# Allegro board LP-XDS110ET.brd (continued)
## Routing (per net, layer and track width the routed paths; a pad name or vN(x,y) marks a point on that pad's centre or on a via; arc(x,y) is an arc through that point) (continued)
ET_PM2: length 40.8
  TOP w0.15: U5.76 13.25,33.17 v1(13.45,32.97) ; v1(45.95,43.97) R96.2 46.2,43.59 U35.17
  BOTTOM w0.15: v1(45.95,43.97) 45.3,43.32 40.56,43.32 39.2,41.96 39.2,41.02 36.66,38.48 36.66,38.47 36.09,37.89 31.96,37.89 28.81,34.75 24.12,34.75 23.32,33.94 14.42,33.94 v1(13.45,32.97)
ET_PN3: length 45.8
  TOP w0.15: v1(5.15,27.47) 4.75,27.47 4.67,27.39 U5.110 ; R114.2 39.43,39.67 v1(40.15,39.67) 40.25,39.77 U35.28
  BOTTOM w0.15: v1(5.15,27.47) 6.5,27.47 8.07,29.03 17.63,29.03 19.69,31.1 28.67,31.1 29.02,30.75 30.78,30.75 30.83,30.69 33.48,30.69 36.52,33.74 37,33.74 37.24,33.99 37.24,34.46 40.15,37.37 v1(40.15,39.67)
ET_SSICLK: length 50.1
  TOP w0.15: v1(43.7,41.67) U35.22 ; v1(5.2,23.92) 4.67,23.39 U5.120
  BOTTOM w0.15: v1(43.7,41.67) 43.7,41.35 41.42,39.07 41.42,38.22 37.54,34.34 37.54,33.86 37.12,33.44 36.65,33.44 33.05,29.85 29.02,29.85 28.31,30.56 25.1,30.56 24.72,30.18 21.21,30.18 20.43,29.4 19.92,29.4 18.4,27.88 9.16,27.88 v1(5.2,23.92)
ET_SSIDAT0: length 50.8
  TOP w0.15: v1(5.65,22.27) 4.72,22.27 4.64,22.19 U5.123 ; v1(44.2,41.47) U35.21
  BOTTOM w0.15: v1(5.65,22.27) 10.93,27.55 24.12,27.55 25.15,28.57 25.15,28.57 26.01,29.43 28.49,29.43 28.96,28.96 32.59,28.96 36.77,33.14 37.25,33.14 37.84,33.74 37.84,34.21 41.72,38.09 41.72,38.95 44.2,41.42 v1(44.2,41.47)
ET_SSIDAT1: length 52.8
  TOP w0.15: U5.124 4.66,21.79 v1(4.95,21.5) ; U35.20 v1(44.7,41.67)
  BOTTOM w0.15: v1(44.7,41.67) 44.7,40.69 43.15,39.14 43.15,37.04 40.07,33.97 40.07,33.79 39.83,33.55 39.65,33.55 38.74,32.63 38.35,32.63 34.36,28.65 34.21,28.65 34.2,28.64 28.86,28.64 28.36,29.13 26.13,29.13 25.27,28.27 25.27,28.27 24.19,27.19 11,27.19 6.65,22.85 6.65,22.62 5.52,21.5 v1(4.95,21.5)
ET_SSIFSS: length 54
  TOP w0.15: U35.19 45.2,41.5 v1(45.2,41.5) ; v1(6.95,22.12) 6.66,22.41 5.78,23.3 5.25,23.3 4.95,22.99 U5.121
  BOTTOM w0.15: v1(6.95,22.12) 6.95,22.72 11.12,26.89 22.4,26.89 22.73,26.57 27.31,26.57 28.53,27.79 33.95,27.79 33.95,27.79 34.19,27.79 34.2,27.8 34.56,27.8 34.81,28.05 34.81,28.11 35.42,28.72 35.42,29.25 38.51,32.33 38.87,32.33 39.78,33.25 39.95,33.25 40.38,33.67 40.38,33.84 44.88,38.35 44.93,38.35 45.17,38.59 45.17,38.64 45.2,38.67 v1(45.2,41.5)
ET_VDD: length 41.9
  TOP w0.15: R151.2 32.2,28.2 C172.1 32.2,26.97 31.6,26.37 29.4,26.37
  BOTTOM w1: 29.3,25.82 v1(29.3,25.12) ; 29.3,25.82 v1(29.3,26.32) ; 29.3,25.82 v1(28.8,26.32) 28.02,25.54 25.58,25.54 24.53,24.49 11.64,24.49 6.36,19.21 6.36,13.02 P9.1
ET_VREF: length 21.7
  TOP w0.3: U40.6 52.47,38.64 C146.1 51.82,38.64 U40.5 ; v1(41.24,26.22) R121.1 ; U35.9 48.65,37.77 48.95,37.47
  BOTTOM w0.3: v1(41.24,26.22) 42.23,27.21 42.23,27.45 44.7,29.92 44.7,30.76 45.87,31.94 47.08,31.94 49.95,34.8 v1(49.95,37.47)
IRSTN: length 23.9
  TOP w0.15: v1(20.24,34.99) 20.2,34.95 R20.2
  BOTTOM w0.15: v1(20.24,34.99) 19.55,34.99 18.87,34.3 10.88,34.3 8.58,32 4.1,32 2.88,33.23 2.88,33.75 3.48,34.35 3.48,36.31 3.32,36.47 P8.10
ITCK: length 11.6
  TOP w0.15: U5.100 2.93,31.39 v1(1.75,32.57)
  BOTTOM w0.15: P8.4 1.1,39.93 1.1,36.29 1.02,36.22 1.02,34.34 1.1,34.27 1.1,33.22 v1(1.75,32.57)
ITDI: length 10.3
  TOP w0.15: v1(3.3,33.57) 2.7,32.97 2.7,32.52 3.03,32.19 U5.98
  BOTTOM w0.15: v1(3.3,33.57) 3.7,33.57 4.26,34.13 4.42,34.13 4.92,34.63 4.92,37.48 4.56,37.85 4.56,38.37 P8.8
ITDO: length 11.2
  TOP w0.15: v1(3.75,33.07) 3.75,32.67 U5.97
  BOTTOM w0.15: v1(3.75,33.07) 4.51,33.83 4.54,33.83 5.22,34.51 5.22,34.54 5.36,34.68 5.36,37.79 5.41,37.85 5.41,38.23 5.39,38.24 5.39,38.6 5.43,38.63 5.43,40.04 P8.6
ITMS: length 8.4
  TOP w0.15: v1(1.81,33.56) 2.17,33.19 2.17,32.57 2.95,31.79 U5.99
  BOTTOM w0.15: P8.2 1.4,37.69 1.4,36.17 1.32,36.09 1.32,34.47 1.4,34.39 1.4,33.97 v1(1.81,33.56)
LP_VDD: length 10
  TOP w0.5: P7.1 v1(48.66,6.96)
  BOTTOM w0.15: 22.9,8.98 P10.5 ; P10.5 21.82,10.06 ; P10.5 23.98,10.06 ; P10.5 22.9,11.14 ; 9.26,3.97 P9.3 ; P9.3 8.19,5.04 ; P9.3 9.26,6.12 ; P9.3 10.34,5.04
  vias: v1(51.95,18.65) v1(51.95,18.12) v1(52.48,18.12)
LS_VDD: length 15.9
  TOP w0.15: C70.1 22.7,15.56
  TOP w0.2: C488.1 33.77,15.56 33.77,15.93 33.89,16.05 U49.2 ; C72.1 28.2,15.64 U10.2 ; U9.2 39.2,15.73 C74.1 ; 22.7,15.56 U8.2
  TOP w0.3: CR16.8 43.17,15.58 42.87,15.28 v1(42.87,15.1) ; 21.96,15.08 v1(21.96,14.43) ; 21.96,15.08 21.5,15.54 R61.2 ; 21.96,15.08 22.43,15.55 C70.1 ; U33.9 53.75,28.64 v1(53.7,28.69) ; v1(27.56,15.2) 27.82,15.46 27.84,15.46 27.92,15.55 C72.1 ; v1(54.45,24.32) 54.25,24.52 U33.3 ; v1(38.37,15.18) 38.74,15.55 C74.1 ; v1(33.19,15.21) 33.53,15.55 C488.1 ; CR7.8 46.64,15.58 46.34,15.28 v1(46.34,15.15)
  L3 w0.15: 9.26,6.5 P9.2 ; P9.2 9.26,8.66 ; P9.2 8.19,7.58 ; P9.2 10.34,7.58
SW_VDD: length 61.3
  TOP w0.15: U44.5 25.02,24.8 23.22,24.8 R134.2 ; U39.14 56.25,30.77 C140.1 v1(57.03,30.97)
  TOP w0.3: U33.1 53,25.27 C139.1 51.7,25.17 v1(50.75,25.17) ; U38.1 55.35,18.32 55.45,18.42 C114.1 v1(56.35,19.01)
  BOTTOM w0.3: 50.77,19.15 52.52,19.15 53.4,18.27 55.61,18.27 v1(56.35,19.01) 56.6,19.26 56.6,25.2 56.81,25.42 56.81,27.44 56.51,27.75 56.51,28.39 56.5,28.39 56.5,28.81 56.51,28.81 56.51,30.45 v1(57.03,30.97) ; 50.77,19.15 50.77,25.15 v1(50.75,25.17) ; 50.77,19.15 45.21,19.15 43.86,20.5 43.12,20.5 41.58,22.03 33.17,22.03 31.5,23.7 31.44,23.7 30.96,24.18 28.07,24.18 v1(27.55,24.69) v1(26.99,24.69) v1(26.37,24.69)
USB1V8: length 11.3
  TOP w0.15: v1(6.16,36.78) C83.1 5.94,37.21 C85.1 5.95,37.52 U15.15 ; v1(13.11,36.91) 12.98,36.91 12.83,37.06 C84.1 12.77,37.52 U15.26
  L3 w0.15: v1(6.16,36.78) 6.29,36.91 v1(13.11,36.91)
USB_VBUS: length 1.8
  TOP w0.15: v1(14.66,40.57) 14.67,40.57 ; 9.87,42.93 10.41,42.39 R82.2 ; CR6.6 v1(5.46,43.65)
  vias: v1(9.45,45.45) v1(9.45,44.6) v1(9.47,42.93) v1(10.44,45.46) v1(11.42,45.47) v1(12.44,45.47) v1(13.48,45.47) v1(13.48,44.6) v1(13.43,42.99) v1(14.63,41.12)
USBA1V8: length 1.9
  TOP w0.15: C86.1 12.98,38.8 C87.1 12.64,38.96 11.96,38.96 U15.29
USBCLK: length 5.7
  TOP w0.15: v1(6.16,35.61) 6.16,35.11 6.44,34.83 6.61,34.83 6.82,34.62 6.82,34.04 U5.92 ; v1(6.25,38.12) 6.35,38.02 U15.14
  L3 w0.15: v1(6.25,38.12) 6.25,37.72 5.77,37.24 5.77,37 5.74,36.96 5.74,36.61 6.16,36.18 v1(6.16,35.61)
USBD0: length 2.3
  TOP w0.15: U15.24 11.2,35.69 11.25,35.64 U5.81
USBD1: length 2.4
  TOP w0.15: U15.23 10.7,35.69 10.85,35.54 U5.82
USBD2: length 2.4
  TOP w0.15: U5.83 10.45,35.44 10.2,35.69 U15.22
USBD3: length 2.5
  TOP w0.15: U5.84 10.05,35.34 9.7,35.69 U15.21
USBD4: length 2.5
  TOP w0.15: U5.85 9.65,35.22 9.2,35.67 U15.20
USBD5: length 2.5
  TOP w0.15: U15.19 8.7,35.67 9.25,35.12 U5.86
USBD6: length 11
  TOP w0.15: U15.18 v1(8.2,35.37) ; U5.106 4.69,28.99 4.89,28.79 v1(6.47,28.79)
  L3 w0.15: v1(8.2,35.37) 8.2,30.51 v1(6.47,28.79)
USBD7: length 10
  TOP w0.15: v1(6.35,29.41) 5.14,29.41 5.12,29.39 5.01,29.39 4.99,29.37 4.63,29.37 4.61,29.39 U5.105 ; U15.17 7.7,35.5 v1(7.68,35.49)
  L3 w0.15: v1(7.68,35.49) 7.68,30.74 v1(6.35,29.41)
USBDIR: length 12.3
  TOP w0.15: U5.104 v1(4.81,29.79) ; v1(5.85,39.02) 6.33,39.02 6.33,39.02 U15.12
  L3 w0.15: v1(4.81,29.79) 5.21,29.79 5.47,30.05 5.47,31.27 5.14,31.61 5.14,37.63 5.39,37.89 5.39,38.6 5.81,39.02 v1(5.85,39.02)
USBDM: length 11.8
  TOP w0.15: U15.8 7.35,41.22 7.22,41.34 v1(6.14,41.34) 5.85,41.34 5.52,41.68 CR6.4 ; v1(11.59,42.97) 11.75,42.97 12.05,43.27 J1.C7 12.05,44.11 11.82,44.35 11.08,44.35 10.85,44.11 J1.C10
  BOTTOM w0.15: v1(11.59,42.97) 11.59,42.91 11.33,42.64 11.33,42.63 10.03,41.34 v1(6.14,41.34)
USBDP: length 13.3
  TOP w0.15: CR6.5 5.61,42.18 5.91,41.87 6.15,41.87 v1(6.15,41.87) 7.85,41.87 8.2,41.52 U15.7 ; v1(11.05,42.97) 10.99,43.03 10.74,43.03 10.45,43.32 J1.C11 10.45,44.32 10.79,44.66 12.11,44.66 12.45,44.32 J1.C6
  BOTTOM w0.15: v1(6.15,41.87) 9.96,41.87 v1(11.05,42.97)
USBNXT: length 12.6
  TOP w0.15: U15.11 v1(6.22,39.52) ; v1(5.05,30.4) 4.86,30.22 4.63,30.22 4.61,30.19 U5.103
  L3 w0.15: v1(5.05,30.4) 4.76,30.68 4.76,36.94 4.78,36.96 4.78,37.68 4.6,37.86 4.6,38.47 4.58,38.49 4.58,38.81 5.29,39.52 v1(6.22,39.52)
USBSTP: length 7.3
  TOP w0.15: v1(5.82,38.42) 5.88,38.42 6,38.54 6.43,38.54 6.45,38.52 U15.13 ; v1(6.59,35.28) 6.99,35.28 7.25,35.02 U5.91
  L3 w0.15: v1(6.59,35.28) 6.52,35.2 6.35,35.2 6.34,35.19 5.98,35.19 5.74,35.44 5.74,35.66 5.44,35.96 5.44,37.51 5.82,37.89 v1(5.82,38.42)
VCM: length 16.3
  TOP w0.2: 44.45,23.56 R109.2 ; 44.45,23.56 45.59,23.56 48,25.97 R111.2 ; 44.45,23.56 44.45,22.77 43.31,21.63 41.13,21.63 40.6,22.17 R100.1 40.25,22.22 R131.1 38.3,25.02 U41.1
XDS_BID_SCL: length 11.4
  TOP w0.15: 4.28,16.54 v1(4.28,17.65) ; U5.112 v1(4.77,26.59)
  BOTTOM w0.15: v1(4.77,26.59) 4,25.82 4,17.93 v1(4.28,17.65)
XDS_BID_SCL_LS: length 35.8
  TOP w0.3: U50.8 v1(2.33,15.15)
  L3 w0.15: P10.6 21.63,11.33 21.63,8.07 17.25,3.69 8.43,3.69 6.04,6.08 6.04,8.45 1.91,12.58 1.91,14.72 v1(2.33,15.15)
XDS_BID_SDA: length 16.7
  TOP w0.15: U5.111 2.91,26.99 v1(2.89,27.01)
  TOP w0.3: v1(5.09,13.54) 4.79,13.24 4.52,13.24 4.28,13
  BOTTOM w0.15: v1(5.09,13.54) 4.5,13.54 3.21,14.84 3.21,25.67 2.89,25.99 v1(2.89,27.01)
XDS_BID_SDA_LS: length 32
  TOP w0.3: U50.1 v1(2.33,14.14)
  L3 w0.15: P10.4 19.21,11.45 19.21,6.8 16.41,3.99 8.55,3.99 6.34,6.21 6.34,8.58 2.33,12.58 v1(2.33,14.14)
XDS_DIR_GPIO1: length 75.4
  TOP w0.15: U49.4 34.69,17.09 34.54,17.24 v1(34.32,17.24) ; U5.116 4.8,24.99 4.92,24.87 v1(5.32,24.87)
  L3 w0.15: v1(36.86,10.46) 36.86,9.83 30.12,3.09 8.18,3.09 5.44,5.83 5.44,7.52 1.31,11.65 1.31,17.13 1.84,17.66 1.84,20.71 4.09,22.96 4.09,24.14 4.82,24.87 v1(5.32,24.87)
  BOTTOM w0.15: v1(36.86,10.46) 36.09,11.23 35.06,11.23 34.25,12.04 34.25,13.34 34.7,13.79 34.7,14.25 34.16,14.78 33.02,14.78 33.01,14.79 32.05,14.79 31.59,15.25 31.59,16.81 32.62,17.83 33.73,17.83 v1(34.32,17.24)
XDS_DIR_GPIO2: length 64.4
  TOP w0.15: U5.117 4.67,24.59 4.9,24.36 v1(4.91,24.36) ; U49.5 35.94,16.74 36.17,16.51 36.17,15.08 34.25,13.16 v1(34.25,9.07)
  L3 w0.15: v1(4.91,24.36) 4.57,24.02 4.57,22.92 2.18,20.53 2.18,17.57 1.61,17 1.61,11.77 5.74,7.65 5.74,5.96 8.3,3.39 29.73,3.39 34.25,7.91 v1(34.25,9.07)
XDS_GPIO1: length 21.3
  TOP w0.15: U49.7 35.9,17.54 36.05,17.69 36.05,18.95 35.07,19.92 31.7,19.92 31.61,20.02 25.83,20.02 23.29,22.56 23.29,22.77 21.87,24.19 U5.43
XDS_GPIO1_LS: length 21.2
  TOP w0.15: R11.2 31.86,16.48 v1(32.09,16.7) ; CR16.1 43.54,12.45 42.64,11.55 39.19,11.55 P10.18
  TOP w0.2: R11.2 31.46,17.22 R12.1
  BOTTOM w0.15: v1(32.09,16.7) 32.37,16.99 32.99,16.99 35,14.98 35,13.66 34.55,13.22 34.55,12.17 35.16,11.55 37.09,11.55 P10.18
XDS_GPIO2: length 20.5
  TOP w0.15: U5.44 21.9,24.59 23.59,22.89 23.59,22.68 25.96,20.32 31.73,20.32 31.82,20.23 v1(35.36,20.23) ; U49.8 v1(35.36,18.43)
  BOTTOM w0.15: v1(35.36,20.23) 35.36,19.83 35.36,19.83 v1(35.36,18.43)
XDS_GPIO2_LS: length 22.9
  TOP w0.15: CR16.2 44.04,12.53 42.77,11.25 36.95,11.25 P10.16
  TOP w0.2: R13.1 31.43,18.36 31.43,18.37 R10.2 v1(31.43,19.59)
  BOTTOM w0.15: P10.16 35.6,16.64 33.7,18.53 33.15,18.53 32.1,19.59 v1(31.43,19.59)
XDS_GPIO3: length 42.6
  TOP w0.15: R360.2 6.44,15.94 6.83,15.54 6.83,15.42 v1(7.33,14.92)
  TOP w0.2: v1(23.19,17.38) 23.22,17.41 23.49,17.41 23.62,17.54 U8.7 ; v1(20.24,23.64) 20.19,23.64 20.04,23.79 U5.42
  BOTTOM w0.15: v1(20.24,23.64) 11.82,23.64 7.08,18.91 7.08,15.16 v1(7.33,14.92) 7.33,14.16 7.66,13.82 10.39,13.82 15.36,18.79 22.28,18.79 23.19,17.88 v1(23.19,17.38)
XDS_GPIO3_LS: length 52.7
  TOP w0.15: CR16.3 v1(44.54,14.06) ; P10.12 29.03,11.11 27.54,11.11 26.74,10.3 v1(26.74,7.28) 18.42,7.28 16.31,9.4 16.31,14.32 19.8,17.81 R15.1
  BOTTOM w0.15: v1(44.54,14.06) 44.54,10.98 41.12,7.56 33.27,7.56 33.19,7.64 29.31,7.64 28.81,7.15 27.27,7.15 27.14,7.28 v1(26.74,7.28)
XDS_NCS: length 2.2
  TOP w0.15: U5.6 7.25,17.7 6.44,16.88 R360.1
XDS_PICO: length 16.4
  TOP w0.15: U5.11 9.25,19.5 9.27,19.52 9.27,20.43 v1(9.84,20.99) ; R361.1 v1(22.57,22.34)
  BOTTOM w0.15: v1(9.84,20.99) 9.83,20.99 10.13,21.29 18.28,21.29 18.66,21.67 21.24,21.67 21.91,22.34 v1(22.57,22.34)
XDS_POCI: length 9
  TOP w0.15: U5.27 15.65,19.67 v1(15.66,19.68) ; R362.1 v1(22.5,21.43)
  BOTTOM w0.15: v1(22.5,21.43) 20.75,19.68 v1(15.66,19.68)
XDS_RESET: length 21.1
  TOP w0.15: U5.40 22.52,22.99 22.99,22.51 22.99,22.43 25.75,19.67 29.35,19.67 30.23,18.79 30.38,18.79 v1(30.51,18.65) 30.63,18.54 R363.1 ; U10.1 27.8,16.06 27.34,15.6 R58.1
  TOP w0.3: v1(26.82,16.09) 26.82,15.71 R58.1
  BOTTOM w0.15: v1(26.82,16.09) 26.85,16.12 26.85,16.69 28.34,18.18 30.04,18.18 v1(30.51,18.65)
XDS_RESET_LS: length 79.3
  TOP w0.15: U10.15 26.55,17.14 26.31,17.38 v1(26.31,18.13)
  TOP w0.2: CR7.2 47.52,14.2 47.16,13.84 46.9,13.84 v1(46.59,13.53) ; P7.10 53.74,11.56 52.8,10.62 v1(50.93,10.62)
  TOP w0.3: R57.1 v1(29.81,44.07)
  L3 w0.15: v1(29.81,44.07) 29.87,44.13 33.51,44.13 33.81,43.83 33.81,20.6 33.22,20 27.64,20 26.31,18.68 v1(26.31,18.13) ; v1(46.59,13.53) 44.5,11.45 31.91,11.45 P10.11
  BOTTOM w0.15: P10.11 29.47,11.11 29.42,11.11 29.2,11.34 27.35,11.34 26.92,11.77 26.92,14.47 25.99,15.4 25.99,17.81 v1(26.31,18.13)
  BOTTOM w0.2: v1(50.93,10.62) 49.5,10.62 v1(46.59,13.53)
XDS_RX: length 7.5
  TOP w0.15: U8.8 24.18,18.27 24.7,18.79 24.7,19.25 23.76,20.19 U5.33
XDS_RX_LS: length 58.5
  TOP w0.15: R61.1 20.26,15.54 R359.2 ; U8.13 v1(21.63,18.37) 19.87,18.37 16.01,14.51 16.01,9.27 18.43,6.85 27.17,6.85 v1(27.94,7.62)
  TOP w0.2: CR16.6 v1(44.04,17.77) ; P10.9 27.94,10.02 v1(27.94,7.62)
  TOP w0.3: R61.1 v1(20.26,16.44)
  BOTTOM w0.15: v1(20.26,16.44) 21.63,17.81 v1(21.63,18.37)
  BOTTOM w0.2: v1(44.04,17.77) 44.04,10.94 41.26,8.16 28.47,8.16 v1(27.94,7.62)
XDS_SCLK: length 2.4
  TOP w0.15: R365.1 5.67,16.89 6.85,18.07 U5.5
XDS_SWO: length 12.2
  TOP w0.15: U8.9 23.67,18.21 24.22,18.76 24.22,19.3 23.71,19.81 16.21,19.81 15.9,20.11 15.39,20.11 14.85,19.57 U5.25
XDS_SWO_LS: length 48.3
  TOP w0.15: v1(42.99,16.3) 43.51,16.3 CR16.7 ; v1(21.68,19.34) 21.91,19.11 R62.2
  TOP w0.2: U8.12 22.3,19.1 R62.2
  BOTTOM w0.15: v1(42.99,16.3) 43.5,15.78 43.5,10.86 41.2,8.55 32.23,8.55 31.76,9.02 31.76,10.96 31.41,11.31 29.94,11.31 29.46,11.79 28.8,11.79 P10.10 27.98,15.01 27.99,15.02 27.99,15.77 29.79,17.57 30.21,17.57 30.95,18.31 30.95,19.14 30.86,19.23 30.86,21.69 30.34,22.2 24.55,22.2 v1(21.68,19.34)
XDS_TCK: length 45.6
  TOP w0.15: v1(7.85,14.37) 7.24,14.37 5.67,15.94 5.67,15.95
  TOP w0.2: U5.35 v1(20.03,20.99) ; U9.6 v1(41.34,17.14)
  BOTTOM w0.15: v1(41.34,17.14) 40.94,17.14 40.57,16.78 35.99,16.78 34.62,18.15 34.62,18.97 33.58,20.01 33.02,20.01 30.44,22.59 24.45,22.59 23.74,21.88 22.2,21.88 21.31,20.99 v1(20.03,20.99) 14.15,20.99 10.53,17.37 10.53,15.38 9.52,14.37 v1(7.85,14.37)
XDS_TCK_LS: length 31.7
  TOP w0.15: R16.1 36.57,15.06 34.55,13.04 34.55,11.11 P10.15
  TOP w0.2: P7.4 v1(49.93,11.57) ; CR7.6 v1(47.52,17.07)
  L3 w0.15: v1(49.93,11.57) 49.47,11.11 36.65,11.11 P10.15
  BOTTOM w0.2: v1(49.93,11.57) 49.93,13.6 47.52,16.01 v1(47.52,17.07)
XDS_TDI: length 28.1
  TOP w0.15: v1(42.07,17.54) 41.64,17.54 41.62,17.57 41.16,17.57 41.14,17.54 U9.7 ; U5.38 19.78,22.19 19.91,22.06 20.32,22.06 20.34,22.08 20.57,22.08 v1(20.59,22.1) 20.83,22.34 R361.2
  BOTTOM w0.15: v1(42.07,17.54) 41.64,17.54 41.62,17.57 39.44,17.57 39.38,17.63 35.56,17.63 34.92,18.27 34.92,19.1 33.7,20.31 33.14,20.31 30.57,22.89 23.41,22.89 23.41,22.88 21.38,22.88 v1(20.59,22.1)
XDS_TDI_LS: length 31.6
  TOP w0.15: CR7.3 48.02,14.23 43.85,10.06 P10.19
  TOP w0.2: R9.1 v1(36.57,18.09) ; CR7.3 51.31,14.83 52.47,13.67 P7.8
  BOTTOM w0.15: v1(36.57,18.09) 37.46,18.98 38.39,18.98 38.95,18.42 42.33,18.42 42.8,17.95 42.8,17.24 42.37,16.82 42.31,16.82 42.1,16.6 42.1,16.35 42.08,16.34 42.08,16.26 41.87,16.05 41.87,11.25 P10.19
XDS_TDO: length 30.3
  TOP w0.15: U5.37 19.72,21.79 19.75,21.76 20.29,21.76 20.62,21.43 R362.2
  TOP w0.2: U5.37 18.32,21.79 18.29,21.75 v1(18.14,21.75) ; v1(41.13,18.87) 40.56,18.29 40.09,18.29 U9.9
  BOTTOM w0.15: v1(41.13,18.87) 41.13,19.65 40.13,20.66 33.22,20.66 30.69,23.19 23.29,23.19 23.28,23.18 21.25,23.18 21.05,22.99 19.38,22.99 v1(18.14,21.75)
XDS_TDO_LS: length 39.3
  TOP w0.2: U9.12 38.81,18.21 R63.2 38.77,19.11 v1(38.22,18.56) ; P7.6 51.2,11.76 v1(50.93,11.49) ; CR7.5 v1(48.63,16.33)
  L3 w0.15: P10.17 38.14,9.03 38.41,8.76 48.2,8.76 v1(50.93,11.49)
  BOTTOM w0.15: v1(38.22,18.56) 38.65,18.12 42.2,18.12 42.5,17.83 42.5,17.37 42.25,17.12 42.19,17.12 41.8,16.73 41.8,16.48 41.78,16.46 41.78,16.39 41.57,16.18 41.57,15.11 40.25,13.79 40.25,13.78 40,13.53 39.99,13.53 39.29,12.83 39.29,11.21 P10.17
  BOTTOM w0.2: v1(48.63,16.33) 49.18,16.33 50.93,14.59 v1(50.93,11.49)
XDS_TMS: length 12.6
  TOP w0.15: U10.8 29.68,18.83 29.18,19.33 25.47,19.33 23.88,20.92 20.7,20.92 20.21,21.42 19.9,21.42 19.87,21.39 U5.36
XDS_TMS_DIR: length 37.8
  TOP w0.15: U5.24 14.45,17.97 15.52,16.9 15.52,16.12 15.71,15.93 15.71,9.15 18.32,6.53 30.13,6.53 31.68,8.09 31.68,13.93 30.99,14.62 30.16,14.62 30.01,14.77 30.01,16.1 29.68,16.44 U10.5
XDS_TMS_LS: length 44.4
  TOP w0.15: P7.2 48.66,12.17 48.04,11.55 v1(47.14,11.55) 43.98,8.39 33.7,8.39 33.06,9.03 P10.13 ; R65.2 25.72,17.5 25.19,16.98 25.19,16.66 24.63,16.1 24.63,14.35 24.38,14.1 v1(24.38,13.7)
  TOP w0.2: CR7.7 v1(46.53,16.33)
  TOP w0.3: R8.1 25.72,18.06 25.72,18.06 R65.2
  L3 w0.15: v1(24.38,13.7) 24.38,9.64 25.14,8.88 31.88,8.88 P10.13
  BOTTOM w0.2: v1(47.14,11.55) 46.09,12.6 46.09,14.1 46.79,14.79 46.79,15.33 46.53,15.59 v1(46.53,16.33)
XDS_TX: length 9.5
  TOP w0.15: U5.34 19.87,20.59 19.9,20.56 23.81,20.56 25.13,19.24 25.13,18.62 24.89,18.38 24.89,17.25 24.78,17.14 U8.6
XDS_TX_LS: length 43.9
  TOP w0.15: CR16.5 v1(45.03,16.33)
  TOP w0.2: R14.1 20.2,17.11 19.22,16.12 19.22,12.17 19.96,11.43 24.07,11.43 P10.7
  BOTTOM w0.15: v1(45.03,16.33) 45.03,15.93 45.05,15.91 45.05,9.31 42.53,6.79 30.73,6.79 30.36,6.42 26.38,6.42 25.44,7.36 P10.7
XDS_VDD: length 60.4
  TOP w0.15: 12.76,40.62 12.76,40.26 12.53,40.02 U15.31 U15.30 ; 12.76,40.62 C80.1 ; 12.76,40.62 13.06,40.32 13.42,40.32 13.51,40.22 v1(13.57,40.22) ; U15.6 8.7,41.87 8.67,41.9 R83.1 ; R17.2 18.87,34.76 18.52,35.11 v1(18.13,35.11) ; 6.45,36.16 6.72,35.89 v1(6.72,35.79) ; 6.45,36.16 C6.1 ; 6.45,36.16 6.5,36.16 7,36.67 U15.16 ; R83.1 8.67,42.71 v1(8.52,42.86) ; R83.1 C79.1 ; C39.1 15.15,35.57 15.63,35.09 15.77,35.09 16.05,34.81 U5.69 ; C39.1 15.25,35.58 15.81,36.14 R31.2 ; C39.1 14.72,35.14 v1(14.38,35.14) ; v1(1.65,26.37) C4.1 ; U5.122 5.32,22.59 v1(5.6,22.87) ; v1(12.18,36.29) 12.76,36.29 C78.1 12.83,36.25 12.42,36.65 12.42,36.77 12.17,37.02 U15.25 ; v1(20.21,25.87) 20.13,25.79 U5.47 ; C7.1 C42.1 8.15,16.87 8.57,16.45 R18.2 v1(8.85,15.77) ; R27.1 22.6,31.62 v1(22.85,31.87) ; R39.1 v1(22.84,32.42) ; U5.79 12.05,34.81 12.69,35.45 v1(13.2,35.45)
  TOP w0.2: U5.7 U5.8 8.05,17.79 8.05,17.44 C42.1 ; v1(16.08,16.68) 16.08,16.76 16.05,16.79 C2.1 ; C3.1 2.79,31.07 2.87,30.99 U5.101 ; U10.4 29,15.57 C73.1 28.8,15.55 28.6,15.75 U10.3 ; C71.1 23.5,15.56 ; 23.5,15.56 U8.4 ; 23.5,15.56 23.1,15.96 U8.3 ; C2.1 16.04,17.25 15.63,17.67 15.63,17.74 15.3,18.07 15.3,18.1 15.25,18.15 U5.26 ; C2.1 16.05,17.87 16.05,17.87 U5.28 ; U5.16 11.25,19.52 10.8,19.97 v1(10.55,19.97) ; U5.90 7.65,33.38 7.14,32.87 v1(7.05,32.87) ; U49.3 34.29,16.05 34.5,15.84 C487.1 ; v1(21.65,28.12) C40.1 C38.1 19.98,27.47 19.9,27.39 U5.51 U5.52 ; U5.39 19.93,22.59 20.01,22.51 20.1,22.51 v1(20.12,22.49) ; U9.4 40,15.78 C75.1 39.6,15.71 U9.3 ; U5.113 2.91,26.19 2.73,26.37 C4.1
  TOP w0.3: v1(25.42,15.74) 25.56,15.74 25.71,15.6 R58.2 ; C487.1 34.64,15.55 34.88,15.78 35,15.78 v1(35.05,15.83) ; v1(24.08,15.89) 23.74,15.55 C71.1 ; C3.1 v1(1.72,31.07) ; v1(4.24,11.74) C11.1 3.63,11.81 U50.3 ; C73.1 29.25,15.55 v1(29.54,15.83) ; C75.1 40.17,15.55 v1(40.45,15.83) ; U50.6 v1(3.63,15.53)
  L3 w1: v1(3.63,15.53) 3.63,14.7 4.05,14.29 4.05,14.27 4.24,14.08 v1(4.24,11.74)
  BOTTOM w0.15: v1(2.58,37.81) 2.58,37.73 2.56,37.71 2.56,37.53 P8.1
  vias: v1(22.72,36.47) v1(23.52,35.98) v1(23.52,35.42) v1(24.14,35.98) v1(24.14,35.42)
N2777344: length 2.7
  TOP w0.15: R57.2 29.04,45.46 29.06,45.48 SW3.3
N2941019: length 2.1
  TOP w0.15: R90.2 4.77,35.7 5.65,34.82 U5.95
N2941087: length 1.4
  TOP w0.15: R91.2 4.77,34.19 4.95,34.01 U5.96
N2941323: length 5.2
  TOP w0.15: R25.2 4.25,19.06 4.8,19.61 6.3,19.61 6.45,19.46 U5.4
N2941987: length 6.7
  TOP w0.15: U15.28 12.02,38.4 14.08,38.4 14.3,38.61 R87.2 14.84,38.62 15.47,39.25 15.47,39.25 15.72,39.5 15.72,39.5 15.79,39.57 16.09,39.57 16.19,39.48 C89.1 17.05,39.48 Y4.1
N2942075: length 8.6
  TOP w0.15: Y4.3 19.75,36.4 18.55,37.6 16.4,37.6 16.38,37.62 C88.2 15.44,37.62 15.38,37.69 R87.1 14.39,37.69 14.06,38.02 U15.27
N2942253: length 1.1
  TOP w0.15: U15.5 9.2,41.87 9.23,41.9 R83.2
N2942419: length 2.7
  TOP w0.15: R39.2 21.16,32.42 20.92,32.19 U5.63
N2942527: length 1.5
  TOP w0.15: U15.32 11.9,40.97 12.3,41.37 R84.2
N2942551: length 2.7
  TOP w0.15: R27.2 21.12,31.62 20.95,31.79 U5.62
N2942639: length 2.6
  TOP w0.15: R29.1 21.34,30.67 20.62,31.39 U5.61
N2942779: length 2.8
  TOP w0.15: R30.1 21.34,29.77 20.12,30.99 U5.60
N2943199: length 2.4
  TOP w0.15: R31.1 C46.1 16.64,35.11 16.45,34.92 U5.68
N2943999: length 6.2
  TOP w0.15: 19.2,33.61 R20.1 ; 19.2,33.61 v1(19.2,33.37) ; 19.2,33.61 18.87,33.94 R17.1 ; U5.70 15.65,33.07 v1(15.65,33.07)
  BOTTOM w0.15: v1(15.65,33.07) 16.15,33.57 19,33.57 v1(19.2,33.37)
N2944041: length 6
  TOP w0.15: U5.9 8.45,17.78 8.85,17.38 R18.1 9.6,17.37 C8.1 9.65,16.52 C50.1 10.3,15.87 U6.3
N2944509: length 13.1
  TOP w0.15: U5.88 8.45,32.85 7.67,32.07 5.6,32.07 3.51,34.17 3.51,36.15 3,36.66 1.99,36.66 1.43,37.22 C9.1 1.4,37.24 Y3.1
N2944561: length 14.3
  TOP w0.15: Y3.3 4.7,40.18 4.72,40.16 C1.1 5.17,40.15 4.65,39.63 4.65,39.63 4.53,39.51 4.53,37.45 4.29,37.2 4.18,37.2 3.94,36.95 3.94,36.85 3.81,36.72 3.81,34.37 5.79,32.38 7.38,32.38 8.05,33.05 U5.89
N2944733: length 3.2
  TOP w0.15: R28.2 20.67,29.57 20.67,30 20.09,30.58 20.09,30.59 U5.59
N2986125: length 14.6
  TOP w0.15: U34.6 U34.7 U34.8 44.2,46.32 44.95,47.07
  TOP w0.4: C118.1 44.95,47.07 45,47.02 v1(45,46.47)
  BOTTOM w0.4: v1(34.35,49.22) 38,49.22 40.75,46.47 v1(45,46.47)
N2986433: length 4
  TOP w0.15: R107.2 53.95,22.24 53.78,22.07 R99.2
N2986453: length 4.4
  TOP w0.15: Y5.3 41.1,48.72 41.75,48.07 43.21,48.07 44.2,49.06 U34.1
N2986493: length 0.5
  TOP w0.15: U34.2 U34.3
N2986501: length 1
  TOP w0.15: R94.2 U34.5
N2986505: length 1.6
  TOP w0.15: U35.24 R94.1
N2986529: length 15.3
  TOP w0.15: R107.1 53.95,20.9 53.68,21.17 R108.2
  TOP w0.3: 55.15,20.12 55.15,20.32 57.05,22.22 57.05,27.11 55.5,28.66 55,28.66 54.75,28.41 U33.7
N2986711: length 5.8
  TOP w0.15: R101.1 43.45,26.57 C129.1 43.4,26.72 R102.2 42.35,26.72 41.85,27.22 41.85,28.22 R95.2
N2986719: length 3.5
  TOP w0.15: R104.2 42.75,32.87 R103.1 40.5,30.62 R95.1
N2986959: length 4.5
  TOP w0.15: C123.1 42.23,29.57 42.58,29.22 U37.4 43.5,28.77 C130.1 R102.1
N2986967: length 3
  TOP w0.15: R103.2 42.7,31.07 U37.1 42.53,30.72 42.31,30.49 C123.2
N2987171: length 2.5
  TOP w0.15: U35.29 40.32,39.27 40.3,39.24 39.97,39.24 39.96,39.26 39.54,39.26 39.53,39.24 39.32,39.24 39.25,39.17 R97.1
N2987283: length 3.4
  TOP w0.15: U36.3 48.13,22.23 48.14,22.24 48.92,22.24 C132.1 49.13,22.08 ; 49.13,22.08 49.14,22.07 R99.1 ; 49.13,22.08 49.12,22.09 49.12,22.5 C124.2
N2987343: length 1.6
  TOP w0.15: U35.8 46.88,35.64 R98.2
N2987399: length 1.3
  TOP w0.15: U36.1 47.49,18.93 R137.2
N2987403: length 5.4
  TOP w0.15: U36.8 43.23,19.69 43.24,19.69 45.3,19.69 46.47,18.52 R137.1
N2987531: length 3.6
  TOP w0.2: R101.2 43.45,22.72 42.96,22.24 42.09,22.24 U36.6
N2987583: length 2.9
  TOP w0.15: R104.1 42.95,34.17 C131.1 43.7,34.92 U35.3
N2987595: length 1.5
  TOP w0.15: U35.23 43.2,43.55 R105.2
N2987655: length 3.7
  TOP w0.15: 49.15,21.13 49.1,21.19 C132.2 ; 49.15,21.13 49.4,21.13 49.44,21.17 R108.1 ; 49.15,21.13 49.1,21.13 ; 49.1,21.13 49.16,21.07 49.16,20.33 C134.1 ; 49.1,21.13 48.93,20.97 48.63,20.97 48.63,20.96 U36.2
N2987667: length 4.8
  TOP w0.15: R111.1 C133.1 47.25,28.27 v1(47.4,28.42) ; U37.7 45.35,29.72 v1(45.67,30.05)
  BOTTOM w0.15: v1(45.67,30.05) 45.77,30.05 v1(47.4,28.42)
N2987683: length 2.9
  TOP w0.15: U35.4 44.2,34.92 C131.2 44.95,34.17 R113.1
N2987711: length 2.3
  TOP w0.15: U36.5 42.41,23.5 42.41,23.5 40.96,23.5 R100.2
N2987751: length 4.5
  TOP w0.15: R110.1 C130.2 44.4,28.8 U37.6 45.29,29.22 45.64,29.57 C135.1
N2987759: length 3.1
  TOP w0.15: C135.2 45.63,30.49 45.4,30.72 U37.9 45.15,31.05 R112.2
N2987811: length 2.5
  TOP w0.15: U35.2 43.2,35.63 42.14,34.57 C136.1
N2987883: length 5.7
  TOP w0.15: R109.1 44.45,26.57 C129.2 44.5,26.72 R110.2 46.05,27.42 46.05,28.22 R120.2
N2987963: length 1.8
  TOP w0.15: C137.1 48.81,38.88 48.36,38.88 48.25,38.77 U35.11
N2988091: length 3.5
  TOP w0.15: R120.1 47.4,30.57 R112.1 45.1,32.87 R113.2
N2988111: length 1.8
  TOP w0.15: C138.1 41.05,41.27 U35.25
N2988211: length 4.8
  TOP w0.15: R116.2 48.55,36.32 47.35,36.32 46.4,37.27 45.96,37.27 45.7,37.01 U35.7
N2988383: length 2
  TOP w0.15: U35.16 48.13,41.27 R117.2
N2988415: length 1.9
  TOP w0.15: U35.15 48.38,40.77 R118.2
N2988503: length 1.8
  TOP w0.15: U35.12 48.43,39.27 R119.2
N2988673: length 17.1
  TOP w0.15: 54.48,30.64 v1(54.5,30.62) ; v1(54.9,19.07) 54.45,18.62 U38.2
  TOP w0.2: U39.2 54.9,31.07 54.5,30.67 v1(54.5,30.62) ; U39.9 54.1,30.07 54.48,30.45 54.48,30.72 54.45,30.72 54.1,31.07 U39.4
  BOTTOM w0.3: v1(54.9,19.07) 53.15,20.82 53.15,29.27 v1(54.5,30.62)
N2989115: length 3.5
  TOP w0.15: U39.1 55.3,31.94 54.42,32.82 ; 54.42,32.82 C143.1 ; 54.42,32.82 55.8,32.82 R123.2
N2989191: length 1.4
  TOP w0.3: U40.3 52.47,45.92 R136.2
N2989203: length 4.2
  TOP w0.15: R121.2 R126.1 38.5,28.37 ; U41.3 38.5,28.37 ; 38.5,28.37 C147.1
N2989279: length 1.1
  TOP w0.3: U40.4 C145.1
N2989287: length 1.8
  TOP w0.5: C146.2 54.95,39.32 R122.2
N2989331: length 6
  TOP w0.15: C144.1 53.95,34.77 52.25,33.07 R125.2 52.6,32.57 53.45,32.57 53.75,32.27 54.17,32.27 54.5,31.94 U39.3
N2989451: length 3.6
  TOP w0.15: U41.4 36.55,27.12 37.38,26.29 R131.2
N2989545: length 2.7
  TOP w0.15: U39.8 52.25,29.62 C149.1 R130.1
N2992079: length 5.9
  TOP w0.15: U46.8 32.1,33.67 31.57,34.19 29.75,34.19 29.05,33.5 C171.1
N2992279: length 2.8
  TOP w0.15: U42.5 33.3,42.95 R133.2 R132.1 34.47,42.99 C153.2
N2992427: length 2.8
  TOP w0.15: U46.5 32.83,29.37 R152.2 R151.1 33.1,27.44 C172.2
N2992751: length 2
  TOP w0.3: R354.1 34.48,21.75 C166.1 35.39,21.78 FL4.2
N2993203: length 2.1
  TOP w0.15: 22.92,26.87 R134.1 23.21,25.7 U44.4
N3012487: length 1.1
  TOP w0.15: U47.1 15.11,42.29 C108.1
N3014332: length 0.9
  TOP w0.15: U47.7 17.63,41.37 R353.2
N3192940: length 6.5
  TOP w0.15: R23.2 0.96,19 0.95,19 1.46,18.49 4.04,18.49 4.69,17.85 5.93,17.85 6.05,17.97 U5.3
N3267387: length 0.9
  TOP w0.2: U8.15 20.78,17.14 R14.2
N3267505: length 1
  TOP w0.2: U9.14 37.22,17.54 R9.2
N3267702: length 1.4
  TOP w0.2: U10.13 27.13,18.36 26.8,18.68 R8.2
N3268107: length 0.9
  TOP w0.2: U49.14 32.27,17.54 R12.2
N3268153: length 0.8
  TOP w0.2: U49.13 32.81,17.94 R13.2
N3268969: length 1
  TOP w0.2: U8.14 21.03,17.54 R15.2
N3400495: length 1.4
  TOP w0.15: R357.2 12.84,43.11 12.85,43.12 J1.C5
N3400502: length 1.8
  TOP w0.15: J1.C12 10.05,43.29 10.62,42.73 10.64,42.73 11.04,42.32 R358.2
N3455582: length 1.8
  TOP w0.15: U10.6 30.62,17.14 R363.2 R364.1
N3465637: length 1.1
  TOP w0.2: R16.2 37.33,17.14 U9.15
N29414070: length 0.9
  TOP w0.15: CR5.2 2.26,20.91 R25.1
N29414230: length 1
  TOP w0.15: R23.1 0.98,19.98 0.98,20.93
N294220919: length 1.1
  TOP w0.15: U15.4 9.7,42.15 R82.1

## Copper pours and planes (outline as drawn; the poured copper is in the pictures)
5V0 on L3 (solid shape): outline of 2674 points within 22.55,20.57 33.44,50.17
5V0 on TOP: 25.63,43.92 21.25,43.92 21.25,42.8 21.91,42.8 21.91,40.38 22.47,40.38 22.47,38.09 23.65,38.09 23.65,41 23.21,41 23.21,42.8 25.63,42.8
5V0 on TOP: 29.95,22.09 29.95,20.57 33.88,20.57 33.88,22.09
5V0 on TOP: 24.2,33.97 24.2,32.97 26.65,32.97 26.65,33.97
5V0 on BOTTOM: 13.45,6.22 21.55,6.22 21.55,11.36 19.08,11.36 19.08,8.26 15.45,8.26 15.45,14.03 24.82,15.08 26.3,19.52 30.7,19.49 30.7,22 29.7,22 29.7,20.73 25.1,20.73 22.91,15.95 13.45,15.95
GND on TOP (solid shape): 6.2,6.21 0.5,6.21 0.51,10.24 6.19,10.24
GND on BOTTOM (solid shape): 6.19,6.21 0.5,6.21 0.5,10.24 6.19,10.24
GND on TOP: 1.5,0.56 0.79,0.86 0.5,1.56 0.5,49.21 0.78,49.89 1.46,50.17 57.04,50.17 57.72,49.89 58,49.21 58,1.56 57.71,0.86 57,0.56 ; 20 cut-outs
GND on BOTTOM: 1.5,0.56 0.79,0.86 0.5,1.56 0.5,49.21 0.78,49.89 1.46,50.17 57.04,50.17 57.72,49.89 58,49.21 58,1.56 57.71,0.86 57,0.56 ; 6 cut-outs
GND on L2: 1.5,0.56 0.79,0.86 0.5,1.56 0.5,49.21 0.78,49.89 1.46,50.17 57.04,50.17 57.72,49.89 58,49.21 58,1.56 57.71,0.86 57,0.56
(no net) on TOP: 28.17,26.39 25.42,26.39 25.42,24.38 28.17,24.38
(no net) on TOP: 27.2,29.6 25.47,29.6 25.47,27.3 27.2,27.3
(no net) on TOP: 28.8,39.47 28.8,38.22 32.25,38.22 32.25,39.47
(no net) on TOP: 48.25,32.77 48.25,34.57 45.65,34.57 45.65,33.97 46.45,33.97 46.45,32.77
(no net) on TOP: 32.45,39.47 32.45,37.67 35.45,37.67 35.45,37.97 38.35,37.97 38.35,41.97 36.55,41.97 36.55,39.47
(no net) on TOP: 21.15,37.87 21.15,36.22 22.3,36.22 22.3,34.74 25.44,34.74 25.44,36.41 23.6,36.41 23.6,37.87
(no net) on TOP: 43.53,32.32 43.25,32.06 43.25,30.27 44.65,30.27 44.65,31.97 44.33,32.32
(no net) on TOP: 51.55,20.27 56.35,20.27 56.35,19.47 55.05,19.47 54.25,18.72 54.25,17.87 53.65,17.87 53.65,18.72 52.85,19.47 51.55,19.47
(no net) on TOP: 53.1,18.87 53.1,17.87 51.7,17.87 51.7,18.87
(no net) on TOP: 36.75,37.77 36.75,35.77 40.35,35.77 40.35,38.07 39.7,38.07 39.7,37.77
(no net) on TOP: 34.15,49.42 34.15,47.82 39.4,47.82 39.4,49.42
(no net) on TOP: 52.75,45.37 52.75,43.77 54.05,43.77 54.35,43.57 54.35,43.17 56.15,43.17 56.15,45.07 54.45,45.07 54.15,45.37
(no net) on TOP: 52.75,39.07 52.75,37.17 48.65,37.17 48.65,37.87 49.95,37.87 51.52,39.07
(no net) on TOP: 35,47.17 35,45.87 35.78,45.87 36.65,45.16 36.65,42.37 38.35,42.37 38.35,43.97 39.45,43.97 39.45,47.17
(no net) on TOP: 32.95,32.67 35.95,32.67 35.95,34.42 32.95,34.42
(no net) on TOP: 56.35,22.62 51.55,22.62 51.55,23.87 52.65,23.87 53.45,24.62 53.45,25.47 54.05,25.47 54.05,24.62 54.85,23.87 56.35,23.87
(no net) on BOTTOM: 7.7,1.66 7.7,6.62 10.82,6.62 10.82,3.25 21.7,3.25 21.7,11.36 24.24,11.36 24.24,3.25 44.36,3.25 51.32,10.21 51.32,18.87 53.32,18.87 53.32,1.66
(no net) on L3: 22.55,50.17 22.55,37.97 23.65,37.97 23.65,36.41 24.58,36.41 24.58,34.92 23.65,34.92 23.65,20.57 30.55,20.57 30.53,23.95 29.1,23.95 28.23,27.36 33.44,27.37 33.44,50.17
(no net) on L3: 7.7,6.25 7.7,9 14.22,9 14.22,15.39 50.85,15.39 50.91,28.92 58,28.92 58,14.23 16.92,14.23 16.92,6.25
(no net) on L3: 36.75,37.67 36.75,32.67 48.35,32.67 48.35,37.67
(no net) on L3: 34.19,20.32 34.19,50.17 57.04,50.17 57.72,49.89 58,49.21 58,20.32
ET_3V3 on L3 (solid shape): outline of 6080 points within 34.19,20.32 58,50.17
ET_AVDD on L3 (solid shape): outline of 654 points within 36.75,32.67 48.35,37.67
ET_VDD on TOP: 28.55,30.22 28.55,21.35 29.55,21.35 29.55,30.22
ET_VDD on BOTTOM: 29.78,26.8 29.78,24.63 27.99,24.63 27.99,26.8
ET_VREF on TOP (solid shape): 52.65,39.07 52.72,39.04 52.75,38.97 52.75,37.27 52.72,37.2 52.65,37.17 51.1,37.17 51,37.17 48.75,37.17 48.68,37.2 48.65,37.27 48.65,37.77 48.68,37.84 48.75,37.87 48.86,37.87 48.88,37.87 49.1,37.87 49.12,37.87 49.92,37.87 49.95,37.88 49.98,37.89 51.49,39.05 51.52,39.06 51.55,39.07
LP_VDD on BOTTOM (solid shape): outline of 460 points within 7.7,1.66 53.32,18.85
LS_VDD on L3 (solid shape): outline of 1298 points within 7.7,6.25 58,28.92
USB_VBUS on TOP: 16.02,41.56 14.53,41.56 14.35,41.37 14.35,40.38 14.53,40.19 16.02,40.19
USB_VBUS on TOP: 13.85,42.59 13.85,46.22 9.11,46.22 9.11,42.61 9.9,42.61 9.9,43.18 13.02,43.18 13.02,42.59
USB_VBUS on L3: 4.74,43.29 4.74,46.21 15.21,46.21 15.21,40.01 13.97,40.01 13.97,41.97 10.07,41.97 10.07,41.97 8.95,41.97 8.95,43.29
XDS_VDD on L3: 16.3,50.17 23.6,50.17 23.59,36.41 24.51,36.41 24.51,34.94 23.59,34.94 23.57,18 41.13,18 41.13,15.52 0.5,15.52 0.5,49.21 0.78,49.89 1.46,50.17 ; 2 cut-outs
N2944467 on TOP: 25.57,37.34 25.57,34.74 27.49,34.74 27.49,37.34
N2986529 on TOP (solid shape): 56.25,20.27 56.32,20.24 56.35,20.17 56.35,19.57 56.32,19.5 56.25,19.47 55.09,19.47 55.05,19.46 54.99,19.42 54.94,19.42 54.9,19.42 54.85,19.42 54.8,19.41 54.63,19.29 54.55,19.09 54.55,19.08 54.53,19.03 54.5,19 54.4,18.89 54.38,18.88 54.35,18.87 54.22,18.79 54.17,18.64 54.17,18 54.17,17.97 54.14,17.9 54.07,17.87 53.83,17.87 53.76,17.9 53.73,17.97 53.73,18 53.73,18.64 53.72,18.69 53.71,18.75 53.71,18.77 53.74,18.88 53.79,18.98 53.8,19.09 53.8,19.1 53.69,19.34 53.45,19.44 53.34,19.42 53.24,19.37 53.23,19.36 53.18,19.34 53.14,19.33 53.03,19.34 52.99,19.35 52.96,19.37 52.88,19.44 52.85,19.46 52.81,19.47 51.65,19.47 51.58,19.5 51.55,19.57 51.55,20.17 51.58,20.24 51.65,20.27
N2992079 on TOP: 27.25,33.97 27.25,32.97 28.55,32.97 28.55,30.47 29.55,30.47 29.55,33.97
N3010981 on TOP: 17.2,40.63 17.2,40.01 20.55,40.01 20.55,42.64 20.92,42.64 20.92,44.04 19.37,44.04 19.37,40.63

Small or netless copper shapes (teardrops, artwork), in the pictures only: 166 on TOP, 104 on BOTTOM, 32 on L3

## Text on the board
Ref Des/Silkscreen Bottom: 1 2 | GND GND | 5V | 3V3 | <-TXD GND | ->RXD SWO | nRST GPIO3 | TMS GND | TCK GPIO2 | TDO GPIO1 | TDI GND
User.Comments: Rev. B | Milling tool 2.0 mm TYP | RED | BOTTOM LAYER
Ref Des/Silkscreen Top: XDS110 | Out | TGT VDD | EXT. | XDS | LP-XDS110ET | Rev: B | MCU101
XSECTION_CHART: L1: TOP CONDUCTOR - COPPER + PLATING 0.035 MM | *  DIELECTRIC - FR-4 0.175 MM (TOP PRIORITY) | L2: L2 PLANE - COPPER 0.035 MM | *  DIELECTRIC - FR-4 1.11 MM | L3: L3 PLANE - COPPER 0.035 MM | *  DIELECTRIC - FR-4 0.175 MM | L4: BOTTOM CONDUCTOR - COPPER + PLATING 0.035 MM | DESIGN CROSS SECTION CHART | ___________________________ | TOTAL THICKNESS 1.6 MM
PAGE_OUTLINE: MCU101 | LP-XDS110ET
User.27: FIGURE | FINISHED_SIZE | 0.2 | 1.05 | 1.1 | 3.2 | 0.899 | 1.0 | 1.4x0.6 | 1.5x0.6 | DRILL CHART: TOP to BOTTOM | ALL UNITS ARE IN MILLIMETERS | ROTATION | - | 90.000 | PLATED | NON-PLATED | QTY | 701 | 23 | 1 | 4 | 2 | 3
